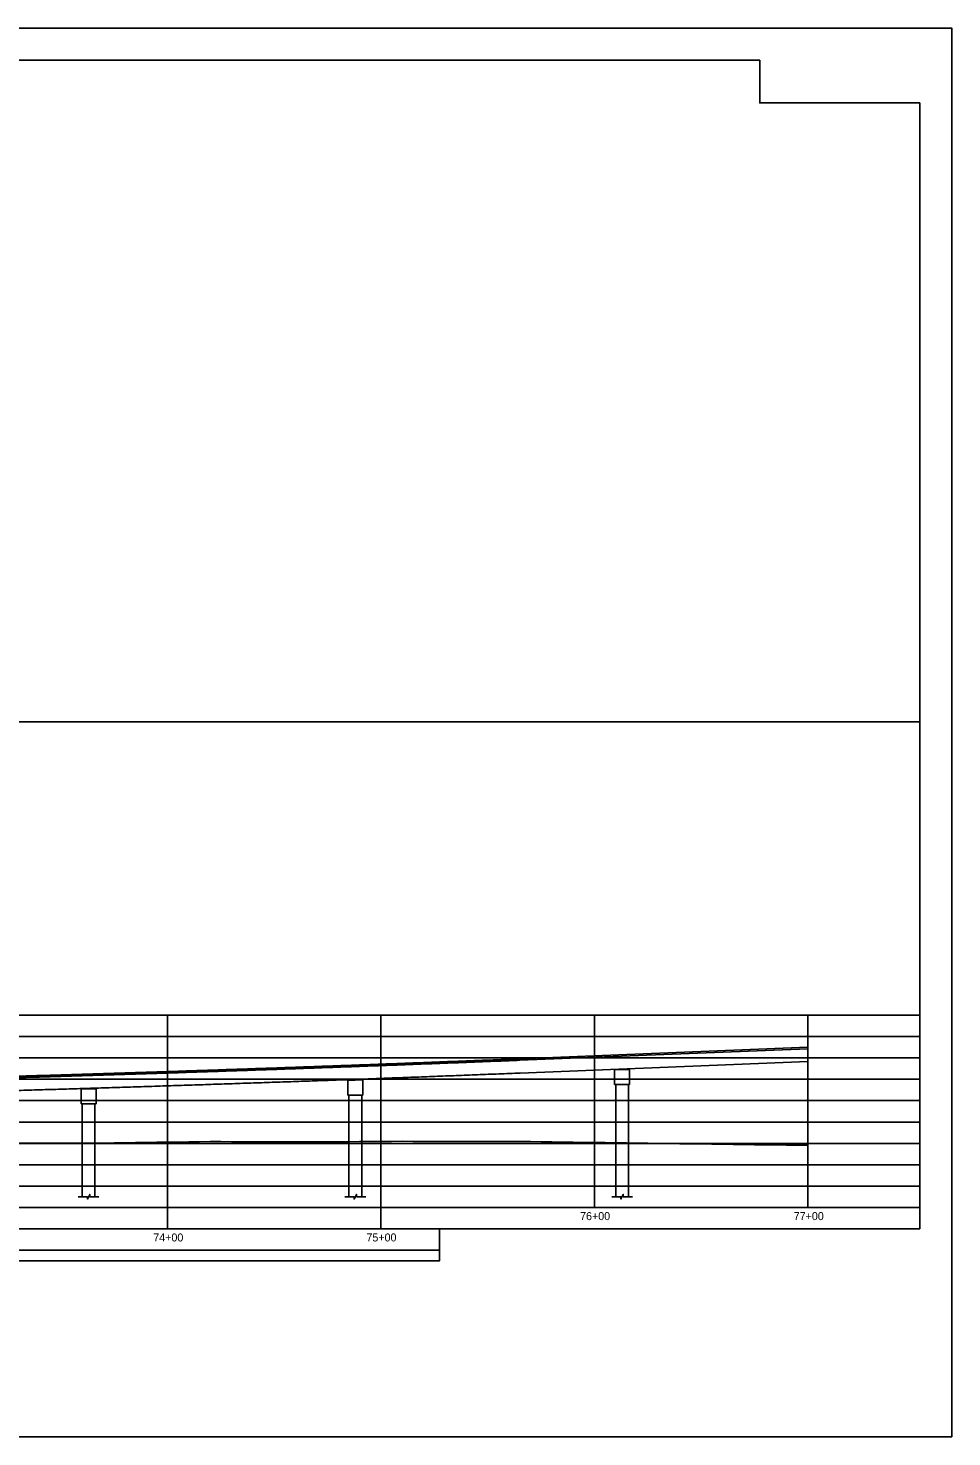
# Model space of a CAD drawing. Extents: x -464 to 4306, y -1372 to 300.
# Drawn here: x 183 to 616, y -1372 to -712 of the extents above; entities that cross this region are included whole.
import ezdxf

# ---------------------------------------------------------------- set-up
doc = ezdxf.new("R2010")
doc.units = 0
for name, color, linetype in [('BR_AUTO DIMENSION', 7, 'Continuous'), ('BR_BORDER LINES', 7, 'Continuous'), ('BR_GRID LINES', 7, 'Continuous'), ('BR_TEXT', 7, 'Continuous'), ('Mis Ground Lines', 7, 'Continuous'), ('NOPLOT', 7, 'Continuous'), ('Sheet Plot Border Outside CELL', 7, 'Continuous'), ('sub interior bent cap lines', 7, 'Continuous'), ('Sup Concrete Girder Lines', 7, 'Continuous'), ('Sup Concrete Slab Lines', 7, 'Continuous')]:
    doc.layers.add(name, color=color, linetype=linetype)

msp = doc.modelspace()

# ---------------------------------------------------------------- linework, layer by layer
at = {"layer": 'BR_AUTO DIMENSION'}
msp.add_line((548.5, -1184.94), (548.5, -1244.94), dxfattribs=at)
for points in [[(206.62, -1259.94), (210.94, -1259.94), (210.94, -1261.06), (212.06, -1258.83), (212.06, -1259.94), (216.37, -1259.94)], [(331.62, -1259.94), (335.94, -1259.94), (335.94, -1261.06), (337.06, -1258.83), (337.06, -1259.94), (341.37, -1259.94)], [(456.62, -1259.94), (460.94, -1259.94), (460.94, -1261.06), (462.06, -1258.83), (462.06, -1259.94), (466.37, -1259.94)]]:
    msp.add_lwpolyline(points, dxfattribs=at)
at = {"layer": 'BR_BORDER LINES'}
msp.add_line((-404, -1037.44), (601, -1037.44), dxfattribs=at)
at = {"layer": 'BR_GRID LINES'}
for p, q in [((-404, -1174.94), (601, -1174.94)), ((248.5, -1274.94), (248.5, -1174.94)), ((348.5, -1274.94), (348.5, -1174.94)), ((448.5, -1264.94), (448.5, -1174.94)), ((548.5, -1264.94), (548.5, -1174.94)), ((-404, -1184.94), (601, -1184.94)), ((-404, -1194.94), (601, -1194.94)), ((-404, -1204.94), (601, -1204.94)), ((-404, -1214.94), (601, -1214.94)), ((-404, -1224.94), (601, -1224.94)), ((-404, -1234.94), (601, -1234.94)), ((-404, -1244.94), (601, -1244.94)), ((-404, -1254.94), (601, -1254.94)), ((-404, -1264.94), (601, -1264.94)), ((-404, -1274.94), (376, -1274.94)), ((-404, -1284.94), (376, -1284.94))]:
    msp.add_line(p, q, dxfattribs=at)
at = {"layer": 'Mis Ground Lines'}
for points in [[(178.5, -1234.81), (183.5, -1234.83), (188.5, -1234.84), (193.5, -1234.82), (198.5, -1234.83), (203.5, -1234.85), (208.5, -1234.85), (213.5, -1234.87), (218.5, -1234.81), (223.5, -1234.74), (228.5, -1234.67), (233.5, -1234.6), (238.5, -1234.53), (243.5, -1234.46), (248.5, -1234.39), (253.5, -1234.32), (258.5, -1234.25), (263.5, -1234.18), (268.5, -1234.15), (273.5, -1234.15), (278.5, -1234.16), (283.5, -1234.17), (288.5, -1234.18), (293.5, -1234.18), (298.5, -1234.19), (303.5, -1234.22), (308.5, -1234.21), (313.5, -1234.2), (318.5, -1234.18), (323.5, -1234.19), (328.5, -1234.19), (333.5, -1234.16), (338.5, -1234.12), (343.5, -1234.08), (348.5, -1234.04)], [(348.5, -1234.04), (353.5, -1234), (358.5, -1233.99), (363.5, -1234), (368.5, -1234.01), (373.5, -1234.02), (378.5, -1234.03), (383.5, -1234.04), (388.5, -1234.05), (393.5, -1234.05), (398.5, -1234.06), (403.5, -1234.08), (408.5, -1234.11), (413.5, -1234.13), (418.5, -1234.15), (423.5, -1234.2), (428.5, -1234.27), (433.5, -1234.34), (438.5, -1234.4), (443.5, -1234.47), (448.5, -1234.54), (453.5, -1234.61), (458.5, -1234.68), (463.5, -1234.75), (468.5, -1234.82), (473.5, -1234.89), (478.5, -1234.96), (483.5, -1235.02), (488.5, -1235.09), (493.5, -1235.16), (498.5, -1235.23), (503.5, -1235.3), (508.5, -1235.37), (513.5, -1235.44), (518.5, -1235.51), (523.5, -1235.57), (528.5, -1235.64), (533.5, -1235.71), (538.5, -1235.78), (543.5, -1235.82), (548.5, -1235.83)]]:
    msp.add_lwpolyline(points, dxfattribs=at)
at = {"layer": 'NOPLOT'}
msp.add_lwpolyline([(-359, -727.45), (-359, -734.19), (-404, -734.19), (-404, -1357.44), (141.93, -1357.44), (141.93, -1289.94), (376, -1289.94), (376, -1274.94), (601, -1274.94), (601, -747.45), (526, -747.45), (526, -727.45)], close=True, dxfattribs=at)
at = {"layer": 'Sheet Plot Border Outside CELL'}
msp.add_lwpolyline([(-464, -712.44), (616, -712.44), (616, -1372.44), (-464, -1372.44)], close=True, dxfattribs=at)
at = {"layer": 'sub interior bent cap lines'}
for p, q in [((465, -1200.29), (458, -1200.57)), ((458, -1200.57), (458, -1207.43)), ((465, -1200.29), (465, -1207.43)), ((340, -1205.17), (333, -1205.42)), ((333, -1205.42), (333, -1212.29)), ((340, -1205.17), (340, -1212.29)), ((458, -1207.43), (465, -1207.43)), ((458.5, -1207.43), (458.5, -1259.94)), ((464.5, -1207.43), (464.5, -1259.94)), ((215, -1209.39), (208, -1209.61)), ((208, -1209.61), (208, -1216.5)), ((215, -1209.39), (215, -1216.5)), ((333, -1212.29), (340, -1212.29)), ((333.5, -1212.29), (333.5, -1259.94)), ((339.5, -1212.29), (339.5, -1259.94)), ((208, -1216.5), (215, -1216.5)), ((208.5, -1216.5), (208.5, -1259.94)), ((214.5, -1216.5), (214.5, -1259.94))]:
    msp.add_line(p, q, dxfattribs=at)
at = {"layer": 'Sup Concrete Girder Lines'}
for p, q in [((413.53, -1196.01), (548.5, -1190.61)), ((413.77, -1202.01), (548.5, -1196.62))]:
    msp.add_line(p, q, dxfattribs=at)
for points in [[(-86.49, -1210.32), (-76.49, -1210.15), (-66.49, -1209.97), (-56.49, -1209.78), (-46.49, -1209.59), (-36.49, -1209.4), (-26.49, -1209.2), (-16.49, -1209), (-6.49, -1208.8), (3.51, -1208.58), (13.51, -1208.37), (23.51, -1208.15), (33.52, -1207.92), (43.52, -1207.69), (53.52, -1207.46), (63.52, -1207.22), (73.52, -1206.98), (83.52, -1206.73), (93.52, -1206.48), (103.52, -1206.22), (113.52, -1205.96), (123.52, -1205.7), (133.52, -1205.43), (143.52, -1205.15), (153.52, -1204.87), (163.52, -1204.59), (173.52, -1204.3), (183.52, -1204.01), (193.52, -1203.71), (203.52, -1203.41), (213.52, -1203.1), (223.52, -1202.79), (233.52, -1202.47), (243.52, -1202.15), (253.52, -1201.83), (263.52, -1201.5), (273.52, -1201.16), (283.52, -1200.83), (293.52, -1200.48), (303.52, -1200.14), (313.52, -1199.78), (323.52, -1199.43), (333.52, -1199.06), (343.52, -1198.7), (353.52, -1198.33), (363.53, -1197.95), (373.53, -1197.57), (383.53, -1197.19), (393.53, -1196.8), (403.53, -1196.41), (413.53, -1196.01)], [(-86.38, -1216.32), (-76.38, -1216.14), (-66.38, -1215.97), (-56.38, -1215.78), (-46.37, -1215.59), (-36.37, -1215.4), (-26.37, -1215.2), (-16.36, -1215), (-6.36, -1214.79), (3.64, -1214.58), (13.65, -1214.37), (23.65, -1214.15), (33.65, -1213.92), (43.65, -1213.69), (53.66, -1213.46), (63.66, -1213.22), (73.66, -1212.98), (83.67, -1212.73), (93.67, -1212.48), (103.67, -1212.22), (113.68, -1211.96), (123.68, -1211.69), (133.68, -1211.42), (143.68, -1211.15), (153.69, -1210.87), (163.69, -1210.59), (173.69, -1210.3), (183.7, -1210), (193.7, -1209.71), (203.7, -1209.4), (213.71, -1209.1), (223.71, -1208.79), (233.71, -1208.47), (243.71, -1208.15), (253.72, -1207.82), (263.72, -1207.5), (273.72, -1207.16), (283.73, -1206.82), (293.73, -1206.48), (303.73, -1206.13), (313.74, -1205.78), (323.74, -1205.42), (333.74, -1205.06), (343.75, -1204.7), (353.75, -1204.32), (363.75, -1203.95), (373.75, -1203.57), (383.76, -1203.19), (393.76, -1202.8), (403.76, -1202.4), (413.76, -1202.01)]]:
    msp.add_spline(points, degree=3, dxfattribs=at)
at = {"layer": 'Sup Concrete Slab Lines'}
msp.add_line((413.5, -1195.34), (548.5, -1189.94), dxfattribs=at)
msp.add_spline([(-86.5, -1209.65), (-76.5, -1209.48), (-66.5, -1209.3), (-56.5, -1209.12), (-46.5, -1208.93), (-36.5, -1208.73), (-26.5, -1208.54), (-16.5, -1208.34), (-6.5, -1208.13), (3.5, -1207.92), (13.5, -1207.7), (23.5, -1207.48), (33.5, -1207.26), (43.5, -1207.03), (53.5, -1206.79), (63.5, -1206.56), (73.5, -1206.31), (83.5, -1206.07), (93.5, -1205.81), (103.5, -1205.56), (113.5, -1205.3), (123.5, -1205.03), (133.5, -1204.76), (143.5, -1204.48), (153.5, -1204.21), (163.5, -1203.92), (173.5, -1203.63), (183.5, -1203.34), (193.5, -1203.04), (203.5, -1202.74), (213.5, -1202.43), (223.5, -1202.12), (233.5, -1201.81), (243.5, -1201.49), (253.5, -1201.16), (263.5, -1200.83), (273.5, -1200.5), (283.5, -1200.16), (293.5, -1199.82), (303.5, -1199.47), (313.5, -1199.12), (323.5, -1198.76), (333.5, -1198.4), (343.5, -1198.03), (353.5, -1197.66), (363.5, -1197.29), (373.5, -1196.91), (383.5, -1196.52), (393.5, -1196.14), (403.5, -1195.74), (413.5, -1195.34)], degree=3, dxfattribs=at)

# ---------------------------------------------------------------- texts
at = {"layer": 'BR_TEXT'}
for s, p in [('76+00', (441.81, -1270.91)), ('77+00', (541.9, -1270.91)), ('74+00', (241.81, -1280.91)), ('75+00', (341.69, -1280.91))]:
    msp.add_text(s, height=3.75, rotation=360, dxfattribs=at).set_placement(p)

doc.saveas('drawing.dxf')
